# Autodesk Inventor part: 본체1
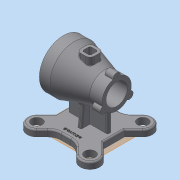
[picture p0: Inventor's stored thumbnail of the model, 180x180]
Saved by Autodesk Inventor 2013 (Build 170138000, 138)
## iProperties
Created: 2018-03
Part Number: 본체1
Material: 일반
Document SubType Name: Modeling
Designer: dgall
Density: 1 g/cm^3
Author: dgall
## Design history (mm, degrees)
sketch "스케치1"
  geometry: L1 (-50, 0)-(50, 0); L2 (-50, 0)-(-50, 45); L3 (-50, 45)-(-30, 45); L4 (27, 27.5)-(50, 27.5); L5 (50, 27.5)-(50, 0); L6 (-30, 45)-(27, 27.5); 1 further point
  constraints: 12 end point, 3 perpendicular, 1 horizontal, 1 midpoint
  dimensions: "d0" = 90 diameter of L2.end L1; "d2" = 20 distance from line of L3.end L2; "d6" = 55 diameter of L4 L1; "d34" = 77 horizontal distance of L2.end L4.start; "d35" = 100 distance between parallel lines of L5 L2; "d36" = 50 distance from line of L5 point (0, 0)
revolve "회전1" sketch "스케치1" stored, may be unused: angle "d11" = 90 deg
sketch "스케치9"
  geometry: L1 (-50, 0)-(50, 0); L2 (50, 35)-(27, 35); L3 (27, 35)-(27, 26); L4 (27, 26)-(-20, 26); L5 (-20, 26)-(-20, 20); L6 (-20, 20)-(-50, 20); L7 (50, 35)-(50, 0); L8 (-50, 20)-(-50, 0); 1 further point
  constraints: 16 end point, 5 parallel, 2 perpendicular, 1 horizontal, 1 midpoint
  dimensions: "d37" = 100 horizontal distance of L2.start L6.end; "d39" = 70 diameter of L2 L1; "d40" = 23 distance of L2.start L2.end; "d41" = 52 diameter of L4 L1; "d42" = 47 distance between parallel lines of L3 L5; "d43" = 40 diameter of L6 L1; "d44" = 27 distance from line of point (0, 0) L3
revolve "회전3" sketch "스케치9" stored, may be unused: angle "d45" = 90 deg
node "작업 평면2"
sketch "스케치10"
  geometry: L1 (-69.444, 0)-(69.444, 0); L2 (0, 48.611)-(0, -44.444); L3 (-12.5, 12.5)-(12.5, 12.5); L4 (12.5, 12.5)-(12.5, -12.5); L5 (12.5, -12.5)-(-12.5, -12.5); L6 (-12.5, -12.5)-(-12.5, 12.5); 2 further points
  constraints: 12 end point, 2 horizontal, 2 midpoint, 2 parallel, 2 perpendicular, 2 point on line
  dimensions: "d47" = 12.5 distance between parallel lines of L1 L3; "d50" = 12.5 distance between parallel lines of L6 L2; "d51" = 12.5 distance between parallel lines of L4 L2; "d60" = 25 distance between parallel lines of L5 L3
extrude "돌출2" join sketch "스케치10" stored distance "d52" = 10; taper "d53" = 0 deg
sketch "스케치11"
  geometry: L1 (-7.5, 7.5)-(7.5, 7.5); L2 (7.5, 7.5)-(7.5, -7.5); L3 (7.5, -7.5)-(-7.5, -7.5); L4 (-7.5, -7.5)-(-7.5, 7.5); 1 further point
  constraints: 8 end point, 2 parallel, 1 horizontal, 1 perpendicular
  dimensions: "d54" = 7.5 distance from line of L4 point (0, 0); "d55" = 7.5 distance from line of point (0, 0) L2; "d56" = 15 distance between parallel lines of L3 L1; "d57" = 7.5 distance from line of L1 point (0, 0)
extrude "돌출3" cut sketch "스케치11" stored distance "d58" = 10; taper "d59" = 0 deg
fillet "모깎기1" dims "d61" = 8
fillet "모깎기2" dims "d62" = 3
fillet "모깎기3" dims "d63" = 1
node "작업 평면3"
sketch "스케치12"
  geometry: L1 (-45, 45)-(45, 45); L2 (45, 45)-(45, -45); L3 (45, -45)-(-45, -45); L4 (-45, -45)-(-45, 45); L5 (-45, 0)-(45, 0); L6 (60.483, 35.239)-(45, 19.755); L7 (35.239, 60.483)-(19.755, 45); L8 (-65.473, 65.473)-(65.473, -65.473); L9 (62.225, 62.225)-(-62.512, -62.512); L10 (-40.017, 65.473)-(-19.544, 45); L11 (-65.473, 40.017)-(-45, 19.544); L12 (-25.456, 0)-(36.77, 62.225); L13 (-37.056, -62.512)-(-19.544, -45); L14 (0, -25.456)-(62.225, 36.77); L15 (0, 25.456)-(25.456, 0); L16 (45, -19.544)-(65.473, -40.017); L17 (-25.456, 0)-(0, -25.456); L18 (19.544, -45)-(40.017, -65.473); L19 (-62.512, -37.056)-(-33, -7.544); A1 r 70 centre (0, 0) between (60.483, 35.239) and (35.239, 60.483); A2 r 18 centre (-52.745, 52.745) between (-36.227, 59.897) and (-59.897, 36.227); A3 r 18 centre (-49.784, -49.784) between (-62.512, -62.512) and (-37.056, -62.512); A4 r 18 centre (49.497, 49.497) between (60.483, 35.239) and (35.239, 60.483); A5 r 18 centre (52.745, -52.745) between (65.473, -65.473) and (40.017, -65.473); 5 further points
  constraints: 38 end point, 20 point on circle, 18 parallel, 15 point on line, 6 midpoint, 5 centre point, 3 perpendicular, 1 coincident, 1 horizontal, 1 tangent
  dimensions: "d65" = 45 distance from line of L4 point (0, 0); "d67" = 45 distance from line of point (0, 0) L1; "d69" = 90 distance between parallel lines of L3 L1; "d70" = 90 distance between parallel lines of L2 L4; "d71" = 140 diameter of A1; "d74" = 36 diameter of A3; "d77" = 36 diameter of A4; "d78" = 36 diameter of A5; "d83" = 45 deg angle of L5 L8; "d86" = 36 diameter of A2; "d87" = 45 deg angle of L5 L9; "d90" = 18 distance between parallel lines of L13 L9
extrude "돌출4" join sketch "스케치12" distance "d92" = 12; taper "d93" = 0 deg
sketch "스케치13"
  geometry: L1 (36.77, 62.225)-(-12.728, 12.728) reference; L2 (-12.728, 12.728)-(-45, 45) reference; L3 (-45, 45)-(-19.544, 45) reference; L4 (-45, 19.544)-(-45, -32.432) reference; L5 (-19.544, 45)-(19.544, 45); 1 further point
  constraints: 2 end point, 1 perpendicular, 1 point on line
extrude "돌출5" join sketch "스케치13" distance "d94" = 12; taper "d95" = 0 deg
sketch "스케치14"
  geometry: L1 (-32.432, -45)-(19.544, -45) reference; L2 (-65.473, 40.017)-(-45, 19.544) reference; L3 (-45, 19.544)-(-45, -32.432) reference; L4 (-37.056, -62.512)-(-19.544, -45); L5 (-62.512, -37.056)-(-45, -19.544); A1 r 18 centre (-49.784, -49.784) between (-45, -32.432) and (-32.432, -45) reference; 1 further point
  constraints: 4 end point, 2 point on circle, 2 point on line, 1 parallel, 1 perpendicular
  dimensions: "d96" = 18 distance from line of L4 point (0, 0); "d97" = 18 distance from line of point (0, 0) L5
extrude "돌출6" join sketch "스케치14" distance "d98" = 12; taper "d99" = 0 deg
fillet "모깎기4" dims "d100" = 25
sketch "스케치18"
  geometry: L1 (-45, 19.544)-(-45, -19.544) reference; L2 (0, 0)-(-37, 0); L3 (0, 0)-(37, 0); L4 (-37.056, -4)-(36.944, -4); L5 (-37.056, 4)-(36.944, 4); L6 (-37.056, 4)-(-37.056, -4); L7 (36.944, 4)-(36.944, -4)
  constraints: 12 end point, 2 equal length, 2 perpendicular
  dimensions: "d111" = 4 distance between parallel lines of L5 L2; "d112" = 4 distance between parallel lines of L2 L4; "d115" = 74 distance between parallel lines of L6 L7
extrude "돌출7" join sketch "스케치18" stored distance "d116" = 12; taper "d117" = 0 deg
sketch "스케치20"
  geometry: L1 (-24, -109.58)-(-24, -45); L2 (-24, -109.58)-(-18, -41); L3 (-19.544, -70)-(-37.056, -70) reference; 1 further point
  constraints: 4 end point, 2 point on line, 1 vertical
  dimensions: "d118" = 24 distance from line of point (0, 0) L1; "d119" = 95 deg angle of L3 L2
feature "리브1" sketch "스케치20" dims "d120" = 1, "d121" = 8, "d122" = 0, "d123" = 0, "d124" = 1, "d125" = 1
sketch "스케치21"
  geometry: L1 (24, -38)-(24, -138.301); L2 (24, -138.301)-(14, -24); L3 (19.544, -70)-(36.77, -70) reference; 1 further point
  constraints: 4 end point, 2 point on line, 1 vertical
  dimensions: "d126" = 24 distance from line of point (0, 0) L1; "d127" = 95 deg angle of L3 L2
feature "리브2" sketch "스케치21" dims "d128" = 1, "d129" = 8, "d130" = 0, "d131" = 0, "d132" = 1, "d133" = 1
fillet "모깎기5" dims "d134" = 3
fillet "모깎기6" dims "d135" = 3
node "작업 평면4"
sketch "스케치24" dims "d139" = 55
  geometry: L1 (-32.921, 0)-(28.532, 0); C1 r 7 at (-27.5, 0); C2 r 7 at (13.75, -23.816); C3 r 7 at (13.75, 23.816); 2 further points
  constraints: 3 centre point, 2 end point, 2 point on line, 1 coincident, 1 horizontal, 1 horizontal alignment, 9 other
  dimensions: "d141" = 14 diameter of C1; "d144" = 360 deg dimension on point (0, 0) C1.centre (derived)
extrude "돌출8" join sketch "스케치24" distance "d146" = 15; taper "d147" = 0 deg
sketch "스케치25"
  geometry: C1 r 2 at (-27.5, 0); C2 r 2 at (13.75, 23.816); C3 r 2 at (13.75, -23.816); A1 r 7 centre (-27.5, 0) between (-26.609, 6.943) and (-26.609, -6.943) reference; A2 r 7 centre (13.75, -23.816) between (7.292, -26.516) and (19.317, -19.573) reference; A3 r 7 centre (13.75, 23.816) between (19.317, 19.573) and (7.292, 26.516) reference
  constraints: 3 centre point, 3 coincident
  dimensions: "d148" = 4 diameter of C1; "d150" = 4 diameter of C3; "d151" = 4 diameter of C2
hole "구멍1" sketch "스케치25" at (-27.5, 0), (13.75, -23.816), (13.75, 23.816) diameter "d152" = 2.459; stored, may be unused: countersink angle "d156" = 90 deg, drill point angle "d158" = 118 deg; dims "d153" = 9, "d154" = 4, "d155" = 2, "d157" = 11
sketch "스케치26"
  geometry: L1 (40, 0)-(-40, 0); C1 r 35 at (0, 0) reference; C2 r 45 at (0, 0) reference; C3 r 2 at (40, 0); C4 r 2 at (20, 34.641); C5 r 2 at (-20, 34.641); C6 r 2 at (-40, 0); C7 r 2 at (-20, -34.641); C8 r 2 at (20, -34.641); A1 r 40 centre (0, 0) between (40, 0) and (-40, 0)
  constraints: 7 centre point, 3 point on circle, 2 end point, 1 coincident, 13 other
  dimensions: "d159" = 80 diameter of A1; "d161" = 4 diameter of C3; "d164" = 360 deg dimension on C1.centre C3.centre (derived)
hole "구멍2" sketch "스케치26" at (40, 0), (20, -34.641), (-20, -34.641), (-40, 0), (-20, 34.641), (20, 34.641) diameter "d166" = 2.459; stored, may be unused: countersink angle "d170" = 90 deg, drill point angle "d172" = 118 deg; dims "d167" = 9, "d168" = 4, "d169" = 2, "d171" = 11
sketch "스케치27"
  geometry: C1 r 10 at (-52.745, 52.745); C2 r 10 at (49.497, 49.497); C3 r 10 at (52.745, -52.745); C4 r 10 at (-49.784, -49.784); A1 r 18 centre (52.745, -52.745) between (40.017, -65.473) and (65.473, -40.017) reference; A2 r 18 centre (49.497, 49.497) between (62.225, 36.77) and (36.77, 62.225) reference; A3 r 18 centre (-52.745, 52.745) between (-40.017, 65.473) and (-65.473, 40.017) reference; A4 r 18 centre (-49.784, -49.784) between (-62.512, -37.056) and (-37.056, -62.512) reference; 1 further point
  constraints: 4 centre point, 4 coincident
  dimensions: "d173" = 20 diameter of C1; "d175" = 20 diameter of C2; "d176" = 20 diameter of C4; "d177" = 20 diameter of C3
extrude "돌출9" cut sketch "스케치27" stored distance "d178" = 15; taper "d179" = 0 deg
fillet "모깎기7" dims "d180" = 3
sketch "스케치28"
  geometry: L1 (-14.152, -32.598)-(14.152, -32.598); L2 (14.152, -32.598)-(14.152, -37.402); L3 (14.152, -37.402)-(-14.152, -37.402); L4 (-14.152, -37.402)-(-14.152, -32.598); L5 (-14.152, -35)-(14.152, -35); L6 (0, -32.598)-(0, -37.402); L7 (45, -19.544)-(45, 19.544) reference; 1 further point
  constraints: 4 end point, 4 midpoint, 2 other
  dimensions: "d181" = 35 distance from line of L5 point (0, 0); "d182" = 45 distance between parallel lines of L7 L6
extrude "돌출10" join sketch "스케치28" distance "d183" = 0.5; taper "d184" = 0 deg
node "솔리드1"
other parameters: "d46" = 45, "d64" = -82, "d84" = 18, "d85" = 18, "d88" = 18, "d89" = 18, "d138" = -15
